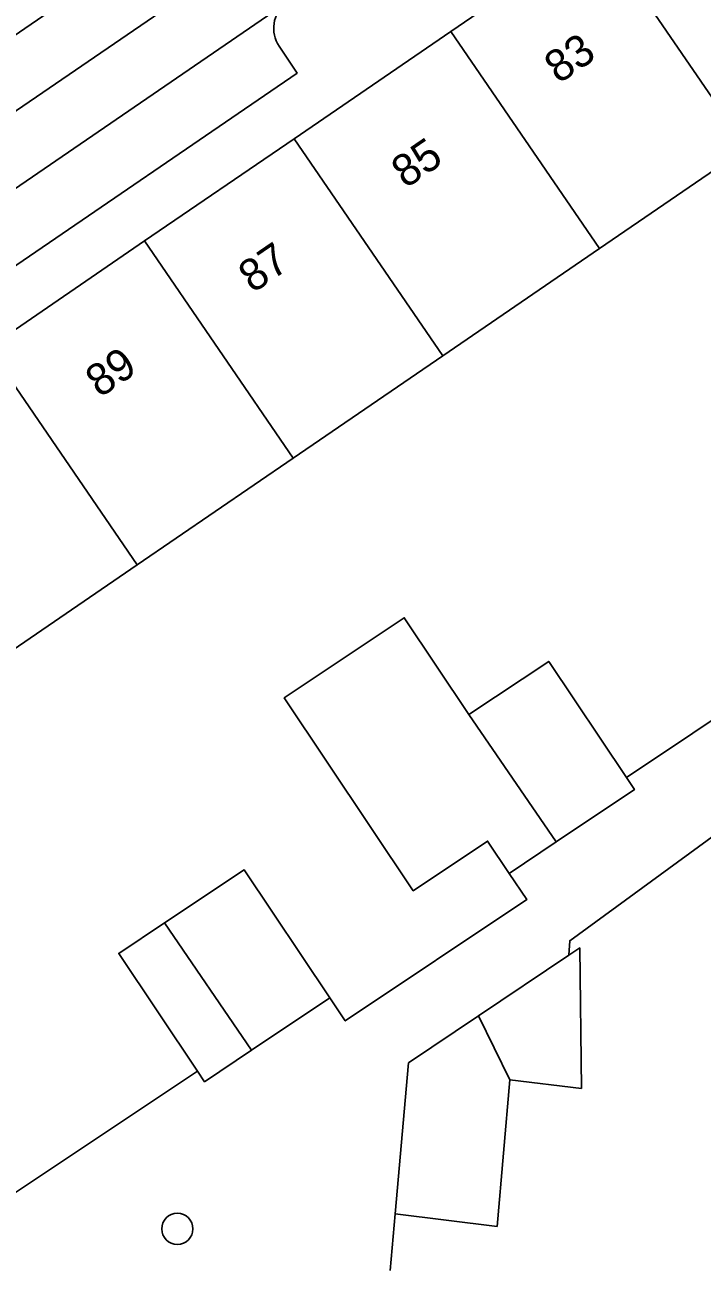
# Model space of a CAD drawing. Extents: x 158087 to 159494, y 382905 to 383981.
# Drawn here: x 158278.93 to 158300.16, y 383370.44 to 383409.32 of the extents above; entities that cross this region are included whole.
import ezdxf

# ---------------------------------------------------------------- set-up
doc = ezdxf.new("R2010")
doc.units = 0
for name, color, linetype in [('IMGEO_Boom', 7, 'Continuous'), ('IMGEO_Fietspad_gesloten', 7, 'Continuous'), ('IMGEO_Pand', 7, 'Continuous'), ('IMGEO_Pand_nummerreeks', 7, 'Continuous'), ('IMGEO_Rijbaan_lokaal_open', 7, 'Continuous'), ('IMGEO_Voetpad_open', 7, 'Continuous')]:
    doc.layers.add(name, color=color, linetype=linetype)

msp = doc.modelspace()

# ---------------------------------------------------------------- linework, layer by layer
at = {"layer": 'IMGEO_Boom'}
msp.add_circle((158283.711, 383371.549), 0.489, dxfattribs=at)
at = {"layer": 'IMGEO_Fietspad_gesloten'}
msp.add_lwpolyline([(158251.53, 383385.606), (158287.104, 383409.987)], dxfattribs=at)
at = {"layer": 'IMGEO_Pand'}
for points in [[(158292.28, 383409.105), (158296.89, 383412.261)], [(158296.89, 383412.261), (158301.675, 383405.273)], [(158287.37, 383405.743), (158292.28, 383409.105)], [(158296.94, 383402.298), (158292.28, 383409.105)], [(158282.682, 383402.534), (158287.37, 383405.743)], [(158292.03, 383398.936), (158287.37, 383405.743)], [(158301.675, 383405.273), (158301.494, 383405.149), (158301.37, 383405.331), (158296.94, 383402.298)], [(158277.79, 383399.184), (158282.682, 383402.534)], [(158282.682, 383402.534), (158287.342, 383395.727)], [(158296.94, 383402.298), (158292.03, 383398.936)], [(158282.45, 383392.378), (158277.79, 383399.184)], [(158292.03, 383398.936), (158287.342, 383395.727)], [(158287.342, 383395.727), (158282.45, 383392.378)], [(158282.45, 383392.378), (158277.796, 383389.192)], [(158292.851, 383387.679), (158290.82, 383390.716), (158287.062, 383388.202), (158291.106, 383382.156), (158293.434, 383383.713), (158294.112, 383382.7)], [(158292.851, 383387.679), (158295.349, 383389.349), (158297.787, 383385.704)], [(158295.585, 383383.686), (158292.851, 383387.679)], [(158297.787, 383385.704), (158298.039, 383385.327), (158295.585, 383383.686)], [(158294.112, 383382.7), (158295.585, 383383.686)], [(158283.306, 383381.145), (158285.803, 383382.814), (158288.493, 383378.792)], [(158284.341, 383376.501), (158281.875, 383380.188), (158283.306, 383381.145)], [(158286.04, 383377.151), (158283.306, 383381.145)], [(158294.135, 383376.229), (158296.373, 383375.957), (158296.321, 383380.363), (158295.978, 383380.132)], [(158295.978, 383380.132), (158293.154, 383378.232)], [(158288.493, 383378.792), (158286.04, 383377.151)], [(158293.154, 383378.232), (158290.956, 383376.753), (158290.541, 383372.019)], [(158293.154, 383378.232), (158294.135, 383376.229)], [(158286.04, 383377.151), (158284.566, 383376.165), (158284.341, 383376.501)], [(158290.541, 383372.019), (158293.731, 383371.629), (158294.135, 383376.229)]]:
    msp.add_lwpolyline(points, dxfattribs=at)
at = {"layer": 'IMGEO_Rijbaan_lokaal_open'}
for points in [[(158136.281, 383311.619), (158143.906, 383316.851), (158156.489, 383325.454), (158158.334, 383326.705), (158177.739, 383340.005), (158216.514, 383366.493), (158235.922, 383379.756), (158248.501, 383388.378), (158270.547, 383403.457), (158288.26, 383415.605), (158296.713, 383421.366)], [(158299.772, 383421.047), (158297.888, 383419.791), (158249.821, 383386.895), (158168.177, 383331.08), (158135.484, 383308.657)]]:
    msp.add_lwpolyline(points, dxfattribs=at)
at = {"layer": 'IMGEO_Voetpad_open'}
for points in [[(158286.897, 383408.645), (158287.462, 383407.8), (158268.632, 383394.92), (158267.975, 383395.886)], [(158297.787, 383385.704), (158304.026, 383389.877)], [(158295.978, 383380.132), (158296.012, 383380.586), (158305.433, 383387.473)], [(158288.493, 383378.792), (158288.973, 383378.075), (158294.661, 383381.88), (158294.112, 383382.7)], [(158278.607, 383372.666), (158284.341, 383376.501)], [(158290.385, 383370.246), (158290.541, 383372.019)]]:
    msp.add_lwpolyline(points, dxfattribs=at)
msp.add_arc((158287.746, 383409.201), 1.015, 129.2359, 213.2269, dxfattribs=at)

# ---------------------------------------------------------------- texts
at = {"layer": 'IMGEO_Pand_nummerreeks'}
for s, p in [('83', (158295.664, 383407.446)), ('85', (158290.87, 383404.164)), ('87', (158286.076, 383400.881)), ('89', (158281.282, 383397.599))]:
    msp.add_text(s, height=1, rotation=34.3972, dxfattribs=at).set_placement(p)

doc.saveas('drawing.dxf')
